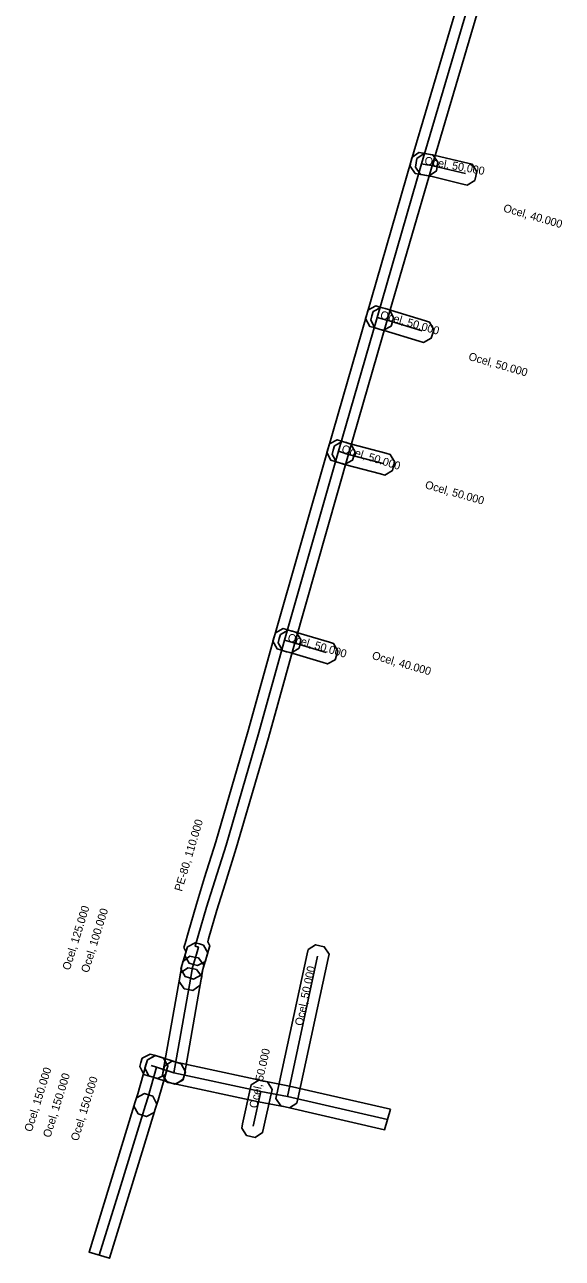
# Model space of a CAD drawing. Extents: x -888412 to -888163, y -1022526 to -1022295.
# Drawn here: x -888252.8 to -888202.5, y -1022526 to -1022410.3 of the extents above; entities that cross this region are included whole.
import ezdxf

# ---------------------------------------------------------------- set-up
doc = ezdxf.new("R2010")
doc.units = 0
for name, color, linetype in [('Vrstva 1', 7, 'Continuous'), ('Vrstva 14', 7, 'Continuous'), ('Vrstva 20', 7, 'Continuous')]:
    doc.layers.add(name, color=color, linetype=linetype)

msp = doc.modelspace()

# ---------------------------------------------------------------- linework, layer by layer
at = {"layer": 'Vrstva 1'}
msp.add_lwpolyline([(-888208.363, -1022402.149), (-888214.72, -1022423.651), (-888218.879, -1022438.047), (-888222.499, -1022450.606), (-888227.547, -1022468.291), (-888230.018, -1022477.183), (-888233.023, -1022487.529), (-888234.076, -1022490.888), (-888234.842, -1022493.348), (-888235.619, -1022496.027), (-888235.701, -1022496.315), (-888235.698, -1022496.321), (-888235.494, -1022496.685), (-888235.609, -1022497.087), (-888235.799, -1022497.747), (-888235.914, -1022498.145), (-888236.639, -1022498.546), (-888237.037, -1022498.431), (-888237.435, -1022498.316), (-888237.836, -1022497.591), (-888237.73, -1022497.224), (-888237.732, -1022497.22), (-888237.936, -1022496.856), (-888237.822, -1022496.455), (-888237.541, -1022495.473), (-888236.758, -1022492.772), (-888235.984, -1022490.292), (-888234.937, -1022486.951), (-888231.942, -1022476.637), (-888229.473, -1022467.749), (-888224.421, -1022450.054), (-888220.801, -1022437.493), (-888216.64, -1022423.089), (-888210.277, -1022401.571)], dxfattribs=at)
for points in [[(-888216.59, -1022422.784), (-888215.91, -1022422.312), (-888215.502, -1022422.386), (-888215.011, -1022422.475), (-888214.603, -1022422.549), (-888214.131, -1022423.229), (-888214.205, -1022423.637), (-888214.279, -1022424.045), (-888214.959, -1022424.517), (-888215.367, -1022424.443), (-888215.858, -1022424.354), (-888216.266, -1022424.28), (-888216.738, -1022423.6), (-888216.664, -1022423.192)], [(-888216.096, -1022422.869), (-888215.413, -1022422.4), (-888215.006, -1022422.476), (-888214.51, -1022422.568), (-888214.385, -1022422.593), (-888211.327, -1022423.328), (-888210.924, -1022423.425), (-888210.491, -1022424.13), (-888210.588, -1022424.533), (-888210.685, -1022424.936), (-888211.39, -1022425.369), (-888211.793, -1022425.272), (-888214.815, -1022424.547), (-888214.89, -1022424.532), (-888215.372, -1022424.442), (-888215.779, -1022424.366), (-888216.248, -1022423.683), (-888216.172, -1022423.276)], [(-888220.686, -1022437.094), (-888219.96, -1022436.694), (-888219.562, -1022436.809), (-888219.081, -1022436.948), (-888218.683, -1022437.063), (-888218.283, -1022437.789), (-888218.398, -1022438.187), (-888218.513, -1022438.585), (-888219.239, -1022438.985), (-888219.637, -1022438.87), (-888220.118, -1022438.731), (-888220.516, -1022438.616), (-888220.916, -1022437.89), (-888220.801, -1022437.492)], [(-888220.201, -1022437.229), (-888219.474, -1022436.833), (-888219.076, -1022436.95), (-888218.768, -1022437.041), (-888218.593, -1022437.092), (-888215.308, -1022438.093), (-888214.912, -1022438.214), (-888214.522, -1022438.946), (-888214.643, -1022439.342), (-888214.764, -1022439.738), (-888215.496, -1022440.128), (-888215.892, -1022440.007), (-888219.167, -1022439.008), (-888219.332, -1022438.959), (-888219.642, -1022438.868), (-888220.039, -1022438.751), (-888220.435, -1022438.024), (-888220.318, -1022437.626)], [(-888224.292, -1022449.638), (-888223.56, -1022449.252), (-888223.164, -1022449.375), (-888222.683, -1022449.524), (-888222.287, -1022449.647), (-888221.901, -1022450.379), (-888222.024, -1022450.775), (-888222.147, -1022451.171), (-888222.879, -1022451.557), (-888223.275, -1022451.434), (-888223.756, -1022451.285), (-888224.152, -1022451.162), (-888224.538, -1022450.43), (-888224.415, -1022450.034)], [(-888223.833, -1022449.815), (-888223.113, -1022449.405), (-888222.714, -1022449.515), (-888222.552, -1022449.559), (-888222.227, -1022449.658), (-888219.003, -1022450.513), (-888218.603, -1022450.619), (-888218.187, -1022451.336), (-888218.293, -1022451.737), (-888218.399, -1022452.137), (-888219.116, -1022452.553), (-888219.517, -1022452.447), (-888222.773, -1022451.582), (-888223.108, -1022451.481), (-888223.244, -1022451.443), (-888223.643, -1022451.333), (-888224.053, -1022450.613), (-888223.943, -1022450.214)], [(-888229.352, -1022467.34), (-888228.624, -1022466.944), (-888228.227, -1022467.061), (-888227.821, -1022467.181), (-888227.815, -1022467.182), (-888227.41, -1022467.271), (-888226.963, -1022467.969), (-888227.052, -1022468.373), (-888227.141, -1022468.778), (-888227.839, -1022469.225), (-888228.243, -1022469.136), (-888228.319, -1022469.119), (-888228.793, -1022468.979), (-888229.19, -1022468.862), (-888229.586, -1022468.134), (-888229.469, -1022467.737)], [(-888228.88, -1022467.49), (-888228.158, -1022467.084), (-888227.759, -1022467.196), (-888227.462, -1022467.279), (-888224.304, -1022468.222), (-888223.907, -1022468.34), (-888223.514, -1022469.069), (-888223.632, -1022469.466), (-888223.75, -1022469.863), (-888224.479, -1022470.256), (-888224.876, -1022470.138), (-888228.018, -1022469.201), (-888228.299, -1022469.122), (-888228.698, -1022469.01), (-888229.104, -1022468.288), (-888228.992, -1022467.889)], [(-888236.081, -1022496.627), (-888235.684, -1022497.354), (-888235.801, -1022497.752), (-888236.171, -1022499.012), (-888236.287, -1022499.409), (-888237.014, -1022499.806), (-888237.412, -1022499.689), (-888237.809, -1022499.573), (-888238.206, -1022498.846), (-888238.089, -1022498.448), (-888237.719, -1022497.188), (-888237.603, -1022496.791), (-888236.876, -1022496.394), (-888236.478, -1022496.511)], [(-888228.856, -1022511.7), (-888229.305, -1022511.004), (-888229.217, -1022510.599), (-888226.377, -1022497.449), (-888226.29, -1022497.044), (-888225.594, -1022496.595), (-888225.189, -1022496.683), (-888224.784, -1022496.77), (-888224.335, -1022497.466), (-888224.423, -1022497.871), (-888227.263, -1022511.021), (-888227.35, -1022511.426), (-888228.046, -1022511.875), (-888228.451, -1022511.787)], [(-888236.549, -1022497.817), (-888236.073, -1022498.495), (-888236.145, -1022498.903), (-888236.335, -1022499.983), (-888236.407, -1022500.391), (-888237.085, -1022500.867), (-888237.493, -1022500.795), (-888237.901, -1022500.723), (-888238.377, -1022500.045), (-888238.305, -1022499.637), (-888238.115, -1022498.557), (-888238.043, -1022498.149), (-888237.365, -1022497.673), (-888236.957, -1022497.745)], [(-888236.738, -1022498.897), (-888236.263, -1022499.576), (-888236.335, -1022499.984), (-888237.885, -1022508.754), (-888237.957, -1022509.162), (-888238.636, -1022509.637), (-888239.044, -1022509.565), (-888239.452, -1022509.493), (-888239.927, -1022508.814), (-888239.855, -1022508.406), (-888238.305, -1022499.636), (-888238.233, -1022499.228), (-888237.554, -1022498.753), (-888237.146, -1022498.825)], [(-888242.226, -1022512.449), (-888242.609, -1022511.714), (-888242.484, -1022511.319), (-888242.248, -1022510.574), (-888241.462, -1022507.788), (-888241.35, -1022507.39), (-888240.627, -1022506.985), (-888240.228, -1022507.098), (-888239.83, -1022507.21), (-888239.425, -1022507.933), (-888239.538, -1022508.332), (-888240.332, -1022511.146), (-888240.576, -1022511.921), (-888240.701, -1022512.316), (-888241.436, -1022512.699), (-888241.831, -1022512.574)], [(-888241.825, -1022507.221), (-888241.093, -1022506.833), (-888240.697, -1022506.954), (-888240.207, -1022507.104), (-888239.811, -1022507.225), (-888239.423, -1022507.957), (-888239.544, -1022508.353), (-888239.665, -1022508.749), (-888240.397, -1022509.137), (-888240.793, -1022509.016), (-888241.283, -1022508.866), (-888241.679, -1022508.745), (-888242.067, -1022508.013), (-888241.946, -1022507.617)], [(-888241.327, -1022507.361), (-888240.591, -1022506.981), (-888240.196, -1022507.107), (-888238.566, -1022507.627), (-888238.171, -1022507.753), (-888237.791, -1022508.489), (-888237.917, -1022508.884), (-888238.043, -1022509.279), (-888238.779, -1022509.659), (-888239.174, -1022509.533), (-888240.804, -1022509.013), (-888241.199, -1022508.887), (-888241.579, -1022508.151), (-888241.453, -1022507.756)], [(-888218.57, -1022512.013), (-888219.134, -1022513.936), (-888228.445, -1022511.789), (-888230.928, -1022511.32), (-888239.081, -1022509.557), (-888239.486, -1022509.47), (-888239.935, -1022508.774), (-888239.847, -1022508.369), (-888239.76, -1022507.964), (-888239.064, -1022507.515), (-888238.659, -1022507.603), (-888230.532, -1022509.36), (-888228.035, -1022509.831)], [(-888230.109, -1022509.454), (-888229.664, -1022510.153), (-888229.754, -1022510.557), (-888230.474, -1022513.797), (-888230.564, -1022514.201), (-888231.263, -1022514.646), (-888231.667, -1022514.556), (-888232.071, -1022514.466), (-888232.516, -1022513.767), (-888232.426, -1022513.363), (-888231.706, -1022510.123), (-888231.616, -1022509.719), (-888230.917, -1022509.274), (-888230.513, -1022509.364)], [(-888243.014, -1022519.863), (-888244.895, -1022525.984), (-888246.815, -1022525.421), (-888244.926, -1022519.277), (-888243.616, -1022514.997), (-888242.486, -1022511.326), (-888242.364, -1022510.93), (-888241.632, -1022510.542), (-888241.236, -1022510.664), (-888240.84, -1022510.786), (-888240.452, -1022511.518), (-888240.574, -1022511.914), (-888241.704, -1022515.583)]]:
    msp.add_lwpolyline(points, close=True, dxfattribs=at)
at = {"layer": 'Vrstva 14'}
for p, q in [((-888209.32, -1022401.86), (-888215.68, -1022423.37)), ((-888215.68, -1022423.37), (-888219.84, -1022437.77)), ((-888215.68, -1022423.37), (-888215.189, -1022423.459)), ((-888219.84, -1022437.77), (-888223.46, -1022450.33)), ((-888219.84, -1022437.77), (-888219.359, -1022437.909)), ((-888223.46, -1022450.33), (-888228.51, -1022468.02)), ((-888223.46, -1022450.33), (-888222.979, -1022450.479)), ((-888236.76, -1022497.47), (-888237.13, -1022498.73)), ((-888228.24, -1022510.81), (-888225.4, -1022497.66)), ((-888237.13, -1022498.73), (-888237.32, -1022499.81)), ((-888237.32, -1022499.81), (-888238.87, -1022508.58)), ((-888240.99, -1022507.91), (-888240.5, -1022508.06)), ((-888240.5, -1022508.06), (-888238.87, -1022508.58)), ((-888238.87, -1022508.58), (-888230.73, -1022510.34)), ((-888230.73, -1022510.34), (-888231.45, -1022513.58)), ((-888230.73, -1022510.34), (-888228.24, -1022510.81)), ((-888228.24, -1022510.81), (-888218.851, -1022512.975))]:
    msp.add_line(p, q, dxfattribs=at)
for points in [[(-888215.189, -1022423.459), (-888214.7, -1022423.55), (-888214.6, -1022423.57), (-888211.56, -1022424.3)], [(-888219.359, -1022437.909), (-888219.05, -1022438), (-888218.88, -1022438.05), (-888215.6, -1022439.05)], [(-888222.979, -1022450.479), (-888222.83, -1022450.52), (-888222.5, -1022450.62), (-888219.26, -1022451.48)], [(-888228.51, -1022468.02), (-888230.98, -1022476.91), (-888233.98, -1022487.24), (-888235.03, -1022490.59), (-888235.8, -1022493.06), (-888236.58, -1022495.75), (-888236.86, -1022496.73), (-888236.57, -1022496.81), (-888236.76, -1022497.47)], [(-888228.51, -1022468.02), (-888228.07, -1022468.15), (-888228.029, -1022468.159)], [(-888228.029, -1022468.159), (-888227.74, -1022468.24), (-888224.59, -1022469.18)], [(-888241.53, -1022511.62), (-888241.29, -1022510.86), (-888240.5, -1022508.06)], [(-888245.855, -1022525.703), (-888243.97, -1022519.57), (-888242.66, -1022515.29), (-888241.53, -1022511.62)]]:
    msp.add_lwpolyline(points, dxfattribs=at)

# ---------------------------------------------------------------- texts
at = {"layer": 'Vrstva 20'}
for s, rotation, p in [('Ocel, 50.000', 349.72595, (-888215.435, -1022423.415)), ('Ocel, 40.000', 343.88671, (-888208.07, -1022427.84)), ('Ocel, 50.000', 343.88172, (-888219.6, -1022437.84)), ('Ocel, 50.000', 343.92172, (-888211.33, -1022441.75)), ('Ocel, 50.000', 342.78852, (-888223.22, -1022450.405)), ('Ocel, 50.000', 344.06673, (-888215.4, -1022453.78)), ('Ocel, 50.000', 343.54001, (-888228.27, -1022468.091)), ('Ocel, 40.000', 344.06673, (-888220.37, -1022469.78)), ('PE-80, 110.000', 73.38191, (-888238.12, -1022491.64)), ('Ocel, 125.000', 72.68795, (-888248.62, -1022499.03)), ('Ocel, 100.000', 72.68795, (-888246.87, -1022499.27)), ('Ocel, 50.000', 77.81306, (-888226.82, -1022504.235)), ('Ocel, 50.000', 77.47117, (-888231.09, -1022511.96)), ('Ocel, 150.000', 72.68795, (-888252.18, -1022514.18)), ('Ocel, 150.000', 72.68795, (-888250.44, -1022514.72)), ('Ocel, 150.000', 72.68795, (-888247.84, -1022515.04))]:
    msp.add_text(s, height=0.75, rotation=rotation, dxfattribs=at).set_placement(p)

doc.saveas('drawing.dxf')
